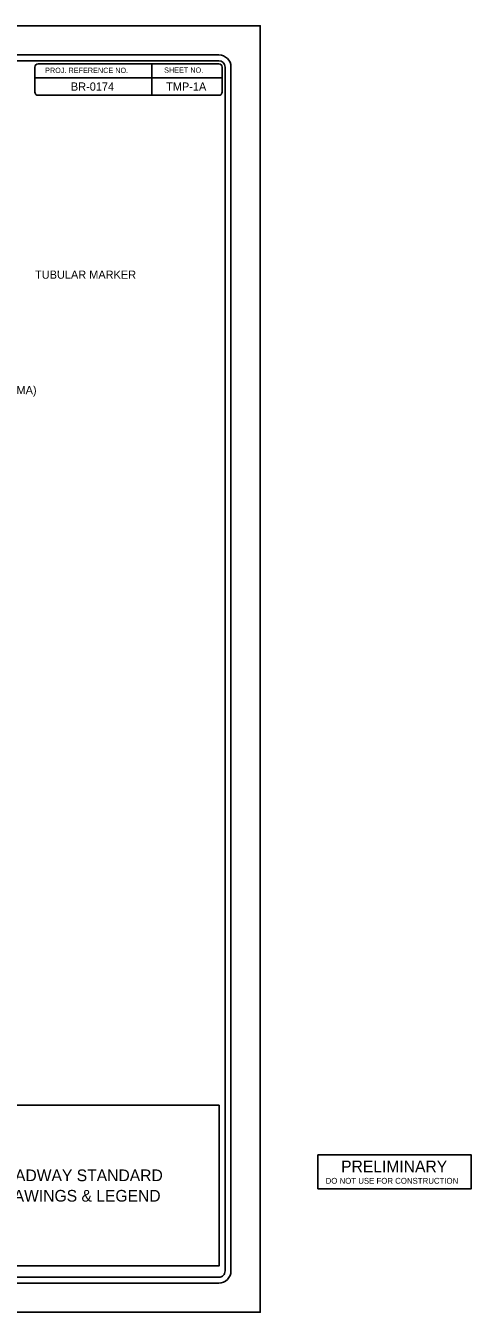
# Model space of a CAD drawing. Extents: x 0 to 1868, y 0 to 1100.
# Drawn here: x 1488 to 1868, y 0 to 1100 of the extents above; entities that cross this region are included whole.
import ezdxf

# ---------------------------------------------------------------- set-up
doc = ezdxf.new("R2010")
doc.units = 0
for name, color, linetype in [('Exist Utilities Sanitary Sewer Test Hole SUE LOS A CELL', 7, 'Continuous'), ('P_RDY_ROW_Permanent_Easement_CELL', 7, 'Continuous'), ('Sheet_RDY_XS_Number', 7, 'Continuous')]:
    doc.layers.add(name, color=color, linetype=linetype)

msp = doc.modelspace()

# ---------------------------------------------------------------- linework, layer by layer
at = {"layer": 'Exist Utilities Sanitary Sewer Test Hole SUE LOS A CELL'}
msp.add_lwpolyline([(0, 0), (1688, 0), (1688, 1100), (0, 1100)], close=True, dxfattribs=at)
at = {"layer": 'P_RDY_ROW_Permanent_Easement_CELL'}
for p, q in [((1652.7, 1075), (173.3, 1075)), ((1652.7, 1070), (740.8, 1070)), ((1498.3, 1067.5), (1652.7, 1067.5)), ((1595.5, 1055.5), (1595.5, 1067.5)), ((1495.5, 1043.3), (1495.5, 1064.8)), ((1655.5, 1064.7), (1655.5, 1062.6)), ((1655.5, 1062.6), (1655.5, 1043.3)), ((1658, 35.3), (1658, 1064.7)), ((1663, 35.3), (1663, 1064.7)), ((1495.5, 1055.5), (1655.5, 1055.5)), ((1595.5, 1040.5), (1595.5, 1055.5)), ((1498.3, 1040.5), (1652.7, 1040.5)), ((173.3, 25), (1652.7, 25)), ((740.8, 30), (1652.7, 30))]:
    msp.add_line(p, q, dxfattribs=at)
msp.add_lwpolyline([(1652.8, 177.1), (1416.8, 177.1), (1416.8, 39.6), (1652.8, 39.6)], close=True, dxfattribs=at)
for centre, radius, start, end in [((1498.3, 1064.7), 2.79, 90.0005, 181.1644), ((1652.7, 1064.7), 10.3, 0.0001, 89.9995), ((1652.7, 1064.7), 5.29, 0.0001, 89.9995), ((1652.7, 1064.7), 2.79, 0.0001, 89.9995), ((1498.3, 1043.3), 2.79, 180.0001, 270.0005), ((1652.7, 1043.3), 2.79, 270.0005, 359.9999), ((1652.7, 35.3), 10.3, 270, 0.0001), ((1652.7, 35.3), 5.29, 270, 0.0001), ((1652.7, 35.3), 5.29, 270, 0.0001)]:
    msp.add_arc(centre, radius, start, end, dxfattribs=at)
at = {"layer": 'Sheet_RDY_XS_Number'}
msp.add_lwpolyline([(1737.3, 134.5), (1868.3, 134.5), (1868.3, 105.6), (1737.3, 105.6)], close=True, dxfattribs=at)
msp.add_lwpolyline([(1737.3, 134.5), (1868.3, 134.5), (1868.3, 105.6), (1737.3, 105.6)], close=True, dxfattribs=at)
msp.add_lwpolyline([(1737.3, 134.5), (1868.3, 134.5), (1868.3, 105.6), (1737.3, 105.6)], close=True, dxfattribs=at)

# ---------------------------------------------------------------- texts
at = {"layer": 'P_RDY_ROW_Permanent_Easement_CELL'}
for s, height, rotation, p in [('PROJ. REFERENCE NO.', 4.489, 0.0006, (1504.2, 1059.6)), ('SHEET NO.', 4.49, 0.0006, (1605.9, 1059.8)), ('TUBULAR MARKER', 7, 359.9598, (1495.6, 883.7)), ('TRUCK MOUNTED ATTENUATOR (TMA)', 7, 359.9598, (1320.1, 785.1))]:
    msp.add_text(s, height=height, rotation=rotation, dxfattribs=at).set_placement(p)
for s, height, p in [('BR-0174', 7, (1526.2, 1044.5)), ('TMP-1A', 7, (1607.6, 1044.5)), ('ROADWAY STANDARD ', 10, (1458.4, 112.1)), ('DRAWINGS & LEGEND', 10, (1458, 94.6))]:
    msp.add_text(s, height=height, dxfattribs=at).set_placement(p)
at = {"layer": 'Sheet_RDY_XS_Number'}
for s, height, p in [(' PRELIMINARY', 10, (1753.4, 119.7)), ('DO NOT USE FOR CONSTRUCTION', 5, (1743.9, 109.9))]:
    msp.add_text(s, height=height, dxfattribs=at).set_placement(p)

doc.saveas('drawing.dxf')
